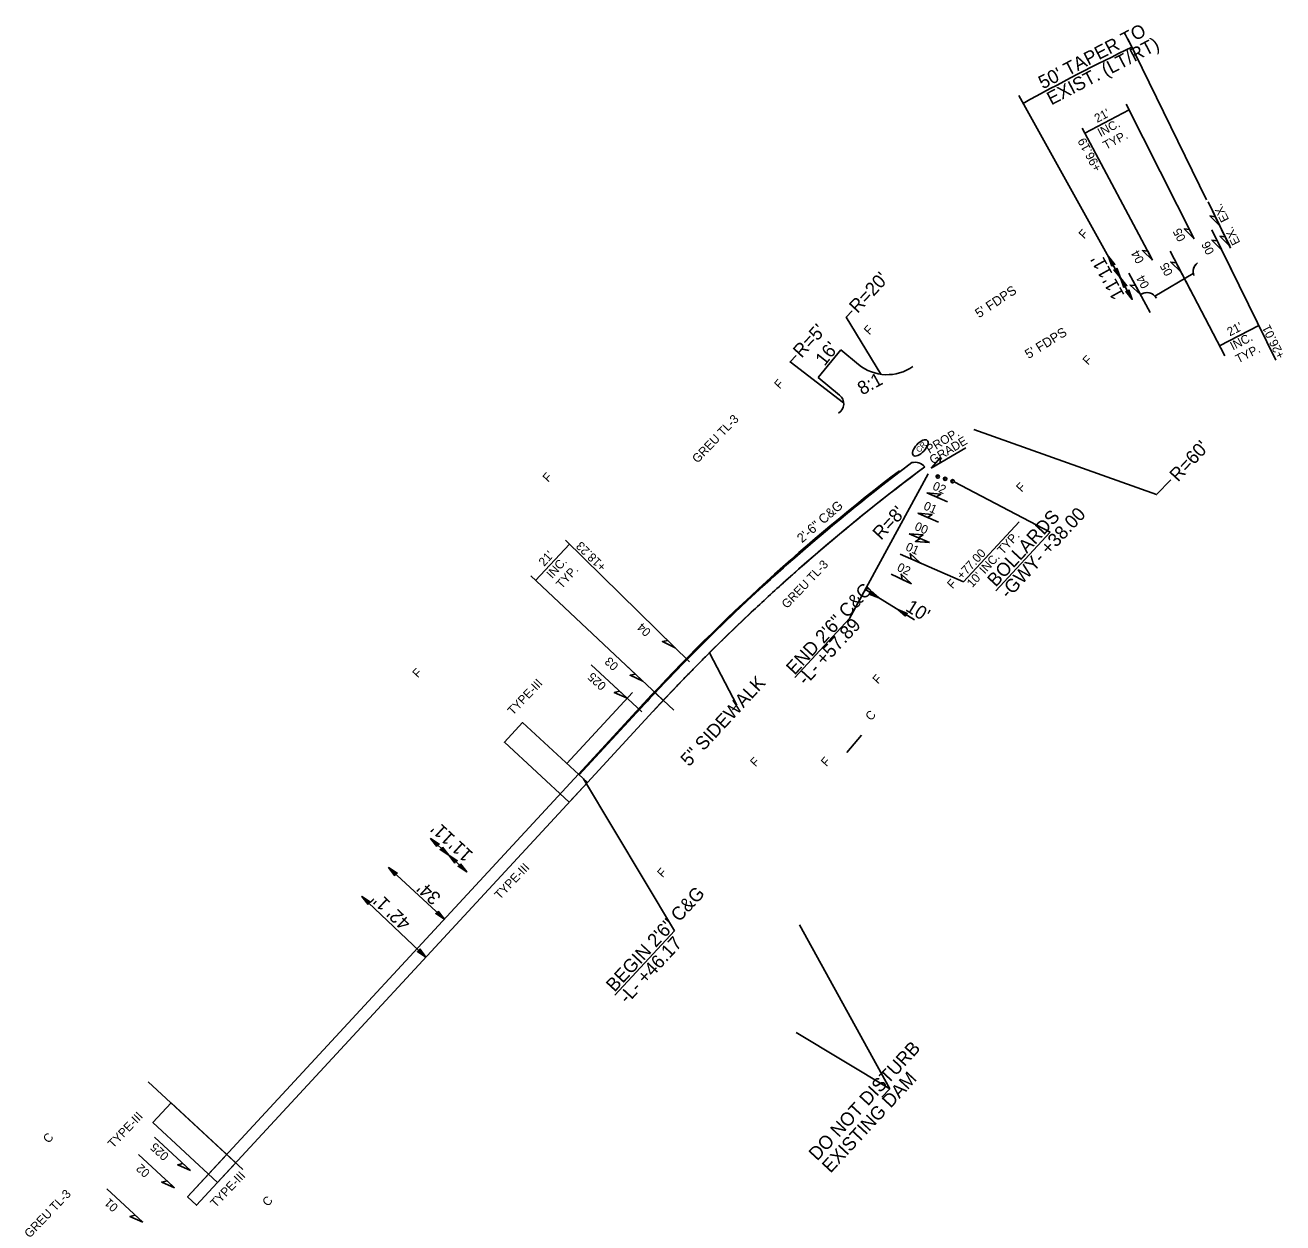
# Model space of a CAD drawing. Extents: x 1768470 to 1769391, y 999727 to 1000666.
# Drawn here: x 1768828 to 1769391, y 1000129 to 1000666 of the extents above; entities that cross this region are included whole.
import ezdxf

# ---------------------------------------------------------------- set-up
doc = ezdxf.new("R2010")
doc.units = 0
for name, color, linetype in [('Cogo Default Point CELL', 7, 'Continuous'), ('COGO Default Point Number', 7, 'Continuous'), ('CTL North Arrow NAD 83 NA 2011 CELL', 7, 'Continuous'), ('CTL North Arrow NAD 83 NSRS CELL', 7, 'Continuous'), ('CTL Sheet Datum Description CELL', 7, 'Continuous'), ('E_ENV_WETLAND_BOUNDARY', 7, 'Continuous'), ('Exist Environmental Wetland Boundary', 7, 'Continuous'), ('Exist Environmental Wetland Boundary Cogo Number', 7, 'Continuous'), ('Exist Hydro Jurisdictional Stream or Body of Water', 7, 'Continuous'), ('Exist Property Line Leader', 7, 'Continuous'), ('P_HYD_TL_Ditch_Lining', 7, 'Continuous'), ('P_HYD_TL_Riprap_Ditch_Bot', 7, 'Continuous'), ('P_NCDOT_Terrain_Contour_Imported', 7, 'Continuous'), ('P_NCDOT_Terrain_Exterior', 7, 'Continuous'), ('Scratch_Level_1', 7, 'Continuous'), ('Scratch_Level_4', 7, 'Continuous'), ('Sheet Symbology CELL', 7, 'Continuous'), ('Sheet Title CELL', 7, 'Continuous')]:
    doc.layers.add(name, color=color, linetype=linetype)

msp = doc.modelspace()

# ---------------------------------------------------------------- linework, layer by layer
at = {"layer": 'Cogo Default Point CELL'}
for p, q in [((1769357.14, 1000587.35), (1769322.01, 1000659.44)), ((1769323.95, 1000542.75), (1769273.09, 1000634.05))]:
    msp.add_line(p, q, dxfattribs=at)
msp.add_arc((1769722.55, 999824.4), 921.98, 115.61226, 119.03268, dxfattribs=at)
at = {"layer": 'CTL North Arrow NAD 83 NA 2011 CELL'}
for points in [[(1769050.9, 1000353.24), (1769079.91, 1000326.43), (1769071.76, 1000317.62), (1769042.76, 1000344.43)], [(1768893.42, 1000182.87), (1768922.43, 1000156.06), (1768914.29, 1000147.25), (1768885.28, 1000174.06)]]:
    msp.add_lwpolyline(points, close=True, dxfattribs=at)
at = {"layer": 'CTL North Arrow NAD 83 NSRS CELL'}
for p, q in [((1769110.26, 1000366.59), (1769113.9, 1000363.16)), ((1769113.9, 1000363.16), (1769110.26, 1000366.59))]:
    msp.add_line(p, q, dxfattribs=at)
msp.add_lwpolyline([(1769109.26, 1000358.18), (1769079.91, 1000326.43), (1769075.87, 1000330.16), (1769076.24, 1000329.82), (1769105.58, 1000361.57)], dxfattribs=at)
msp.add_lwpolyline([(1768900.84, 1000140.8), (1768904.88, 1000137.07), (1769079.91, 1000326.43), (1769075.87, 1000330.16)], close=True, dxfattribs=at)
for centre, radius, start, end in [((1769763.92, 999753.04), 896.5, 126.9363, 136.8132), ((1769226.58, 1000463.78), 6, 41.678, 103.4563), ((1769763.92, 999753.04), 891.5, 126.70564, 130.88594), ((1769763.92, 999753.04), 891.5, 131.89099, 133.23105), ((1769763.92, 999753.04), 891.5, 134.01351, 134.23609), ((1769763.92, 999753.04), 891.5, 134.90564, 134.90612), ((1769763.92, 999753.04), 891.5, 134.57111, 134.57501), ((1769763.92, 999753.04), 891.5, 135.91117, 136.24618), ((1769763.92, 999753.04), 896.5, 136.8132, 137.25123)]:
    msp.add_arc(centre, radius, start, end, dxfattribs=at)
for points, degree in [([(1769180.38, 1000427.03), (1769179.07, 1000425.89), (1769176.45, 1000423.61), (1769172.54, 1000420.16), (1769169.94, 1000417.85), (1769168.65, 1000416.69)], 3), ([(1769153.29, 1000402.58), (1769152.03, 1000401.39), (1769150.76, 1000400.2), (1769149.5, 1000399)], 2), ([(1769145.74, 1000395.4), (1769145.32, 1000394.99), (1769144.9, 1000394.59), (1769144.48, 1000394.18)], 2), ([(1769149.5, 1000399), (1769148.25, 1000397.81), (1769146.99, 1000396.6), (1769145.74, 1000395.4)], 2), ([(1769141.99, 1000391.77), (1769140.75, 1000390.56), (1769139.51, 1000389.35), (1769138.27, 1000388.13)], 2), ([(1769134.57, 1000384.46), (1769133.33, 1000383.23), (1769130.88, 1000380.77), (1769127.22, 1000377.06), (1769124.8, 1000374.57), (1769123.59, 1000373.32)], 3), ([(1769138.22, 1000388.08), (1769137, 1000386.88), (1769135.79, 1000385.67), (1769134.57, 1000384.46)], 2), ([(1769119.97, 1000369.57), (1769118.77, 1000368.31), (1769117.57, 1000367.05), (1769116.38, 1000365.79)], 2), ([(1769112.81, 1000361.99), (1769111.62, 1000360.72), (1769110.44, 1000359.45), (1769109.26, 1000358.18)], 2), ([(1769113.9, 1000363.16), (1769113.54, 1000362.77), (1769113.17, 1000362.38), (1769112.81, 1000361.99)], 2), ([(1769116.38, 1000365.79), (1769115.55, 1000364.92), (1769114.72, 1000364.04), (1769113.9, 1000363.16)], 2)]:
    msp.add_open_spline(points, degree=degree, dxfattribs=at)
at = {"layer": 'CTL Sheet Datum Description CELL'}
for p, q in [((1769197.23, 1000399.86), (1769232.53, 1000464.57)), ((1769244.18, 1000461.02), (1769287.12, 1000438.43)), ((1769262.83, 1000412.15), (1769287.12, 1000438.43)), ((1769226.41, 1000399.2), (1769204.85, 1000412.47)), ((1769172.79, 1000373.42), (1769197.23, 1000399.86)), ((1769134.57, 1000384.46), (1769146.75, 1000360.97)), ((1769144.88, 1000358.94), (1769146.75, 1000360.97)), ((1769118.85, 1000259.99), (1769078.2, 1000328.01)), ((1769009.69, 1000301.29), (1769017.77, 1000293.82)), ((1769017.77, 1000293.82), (1769025.85, 1000286.36)), ((1769015.82, 1000265.2), (1768990.84, 1000288.26)), ((1769007.57, 1000248.17), (1768978.92, 1000275.38)), ((1769092.14, 1000231.1), (1769118.85, 1000259.99)), ((1769215.38, 1000189.23), (1769174.82, 1000262.59)), ((1769215.38, 1000189.23), (1769173.34, 1000214.45)), ((1769215.38, 1000189.23), (1769211.72, 1000185.38))]:
    msp.add_line(p, q, dxfattribs=at)
for points in [[(1769198.55, 1000537.66), (1769195.84, 1000534.73), (1769211.3, 1000509.2)], [(1769173.4, 1000517.67), (1769170.69, 1000514.73), (1769194.67, 1000496.45)], [(1769341.27, 1000461.98), (1769334.81, 1000455.34), (1769253.02, 1000484.49)]]:
    msp.add_lwpolyline(points, dxfattribs=at)
at = {"layer": 'Exist Environmental Wetland Boundary Cogo Number'}
for points in [[(1769314.76, 1000557.66), (1769313.25, 1000561.97), (1769316.15, 1000558.41), (1769315.17, 1000558.52)], [(1769317.09, 1000556.67), (1769318.6, 1000552.36), (1769315.7, 1000555.93), (1769316.68, 1000555.81)], [(1769320.11, 1000548.05), (1769318.6, 1000552.36), (1769321.5, 1000548.8), (1769320.52, 1000548.91)], [(1769322.44, 1000547.06), (1769323.95, 1000542.75), (1769321.05, 1000546.32), (1769322.03, 1000546.2)], [(1769206.95, 1000412.09), (1769210.37, 1000409.07), (1769206.1, 1000410.76), (1769207.01, 1000411.14)], [(1769222.32, 1000400.81), (1769218.89, 1000403.83), (1769223.16, 1000402.13), (1769222.25, 1000401.75)], [(1769012.47, 1000297.66), (1769009.69, 1000301.29), (1769013.56, 1000298.8), (1769012.59, 1000298.61)], [(1769014.99, 1000297.45), (1769017.77, 1000293.82), (1769013.9, 1000296.31), (1769014.87, 1000296.5)], [(1769020.55, 1000290.2), (1769017.77, 1000293.82), (1769021.64, 1000291.34), (1769020.67, 1000291.14)], [(1768993.62, 1000284.64), (1768990.84, 1000288.27), (1768994.71, 1000285.78), (1768993.75, 1000285.59)], [(1769023.07, 1000289.98), (1769025.85, 1000286.36), (1769021.98, 1000288.84), (1769022.95, 1000289.04)], [(1768981.66, 1000271.71), (1768978.93, 1000275.37), (1768982.76, 1000272.84), (1768981.79, 1000272.65)], [(1769013.04, 1000268.82), (1769015.82, 1000265.2), (1769011.96, 1000267.68), (1769012.92, 1000267.88)], [(1769004.84, 1000251.83), (1769007.57, 1000248.17), (1769003.74, 1000250.71), (1769004.71, 1000250.89)]]:
    msp.add_lwpolyline(points, close=True, dxfattribs=at)
at = {"layer": 'Exist Hydro Jurisdictional Stream or Body of Water'}
for p, q in [((1769357.91, 1000586.38), (1769367.97, 1000565.72)), ((1769334.04, 1000544.22), (1769351.27, 1000554.37)), ((1769070.73, 1000334.91), (1769100.08, 1000366.66)), ((1769196.14, 1000339.87), (1769202.59, 1000347.52)), ((1768900.84, 1000140.8), (1768904.88, 1000137.07))]:
    msp.add_line(p, q, dxfattribs=at)
msp.add_lwpolyline([(1768900.84, 1000140.8), (1768900.84, 1000140.8), (1768918.39, 1000159.79)], dxfattribs=at)
for centre, start, end in [((1769356.21, 1000555.12), 127.0126, 199.6474), ((1769356.21, 1000555.12), 127.0126, 188.6168), ((1769330.44, 1000540.75), 30.0937, 124.524), ((1769330.44, 1000540.75), 43.9672, 115.437)]:
    msp.add_arc(centre, 5, start, end, dxfattribs=at)
at = {"layer": 'P_HYD_TL_Ditch_Lining'}
for centre, radius in [((1769236.79, 1000463.34), 0.75), ((1769236.79, 1000463.34), 0.05), ((1769240.13, 1000462.32), 0.75), ((1769240.13, 1000462.32), 0.05), ((1769243.48, 1000461.3), 0.75), ((1769243.48, 1000461.3), 0.05)]:
    msp.add_circle(centre, radius, dxfattribs=at)
at = {"layer": 'P_HYD_TL_Riprap_Ditch_Bot'}
msp.add_ellipse((1769229, 1000476.21), major_axis=(3.11, 3.37), ratio=0.462467, dxfattribs=at)
at = {"layer": 'P_NCDOT_Terrain_Contour_Imported'}
for p, q in [((1769368.41, 1000555.91), (1769359.57, 1000573.85)), ((1769340.84, 1000564.36), (1769350.09, 1000546.62)), ((1769322.34, 1000554.43), (1769331.99, 1000536.92)), ((1769125.58, 1000380.37), (1769111.31, 1000394.39)), ((1769118.64, 1000358.71), (1769096.77, 1000379.25)), ((1769089.61, 1000371.55), (1769104.3, 1000357.97))]:
    msp.add_line(p, q, dxfattribs=at)
at = {"layer": 'P_NCDOT_Terrain_Exterior'}
for p, q in [((1769302.68, 1000617.13), (1769322.54, 1000627.67)), ((1769321.26, 1000630.19), (1769351.68, 1000569.91)), ((1769301.43, 1000619.46), (1769333.04, 1000560.24)), ((1769358.34, 1000585.5), (1769363.16, 1000575.61)), ((1769363.16, 1000575.61), (1769367.59, 1000566.51)), ((1769359.57, 1000573.85), (1769388.29, 1000515.55)), ((1769340.84, 1000564.36), (1769365.33, 1000517.4)), ((1769322.34, 1000554.43), (1769327.6, 1000544.87)), ((1769362.94, 1000521.99), (1769380.64, 1000531.08)), ((1769233.86, 1000467.11), (1769249.39, 1000476.31)), ((1769241.13, 1000452.11), (1769231.96, 1000456.12)), ((1769227.96, 1000446.96), (1769237.12, 1000442.95)), ((1769248.4, 1000416.2), (1769273.33, 1000443.17)), ((1769070.15, 1000434.84), (1769119.16, 1000386.68)), ((1769223.95, 1000437.8), (1769233.11, 1000433.79)), ((1769056.72, 1000416.86), (1769071.9, 1000433.12)), ((1769219.94, 1000428.64), (1769248.4, 1000416.2)), ((1769054.56, 1000418.86), (1769104.79, 1000371.72)), ((1769216, 1000419.65), (1769225.01, 1000415.3)), ((1769081.54, 1000379.01), (1769097.69, 1000364.08)), ((1768886, 1000167.47), (1768902.15, 1000152.54)), ((1768878.87, 1000159.76), (1768895.03, 1000144.83)), ((1768864.62, 1000144.34), (1768880.77, 1000129.41))]:
    msp.add_line(p, q, dxfattribs=at)
for points in [[(1769363.16, 1000575.61), (1769358.73, 1000580.13), (1769361.13, 1000579.76)], [(1769351.68, 1000569.91), (1769347.19, 1000574.37), (1769349.6, 1000574.04)], [(1769367.58, 1000566.51), (1769363.16, 1000571.03), (1769365.56, 1000570.67)], [(1769333.04, 1000560.24), (1769328.45, 1000564.59), (1769330.86, 1000564.32)], [(1769364.03, 1000564.81), (1769359.58, 1000569.31), (1769361.98, 1000568.96)], [(1769345.7, 1000555.05), (1769341.15, 1000559.45), (1769343.56, 1000559.15)], [(1769327.6, 1000544.87), (1769322.96, 1000549.16), (1769325.37, 1000548.92)], [(1769233.86, 1000467.11), (1769238, 1000471.89), (1769237.84, 1000469.47)], [(1769231.96, 1000456.12), (1769238.26, 1000455.55), (1769236.2, 1000454.27)], [(1769227.96, 1000446.96), (1769234.26, 1000446.39), (1769232.19, 1000445.11)], [(1769223.95, 1000437.8), (1769230.25, 1000437.23), (1769228.19, 1000435.95)], [(1769233.11, 1000433.79), (1769226.81, 1000434.36), (1769228.87, 1000435.64)], [(1769229.1, 1000424.63), (1769224.41, 1000428.87), (1769224.87, 1000426.48)], [(1769225.01, 1000415.3), (1769220.47, 1000419.71), (1769220.84, 1000417.31)], [(1769119.16, 1000386.68), (1769113.48, 1000389.46), (1769115.86, 1000389.92)], [(1769104.79, 1000371.72), (1769099.04, 1000374.37), (1769101.42, 1000374.88)], [(1769097.69, 1000364.08), (1769091.93, 1000366.68), (1769094.29, 1000367.22)], [(1768902.15, 1000152.54), (1768896.39, 1000155.14), (1768898.76, 1000155.68)], [(1768895.03, 1000144.83), (1768889.26, 1000147.43), (1768891.63, 1000147.97)], [(1768880.77, 1000129.41), (1768875.01, 1000132.01), (1768877.38, 1000132.55)]]:
    msp.add_lwpolyline(points, close=True, dxfattribs=at)
at = {"layer": 'Scratch_Level_1'}
for p, q in [((1769239.88, 1000461.75), (1769240.15, 1000462.36)), ((1769075.87, 1000330.16), (1769105.22, 1000361.91)), ((1769075.87, 1000330.16), (1769105.22, 1000361.91)), ((1769075.87, 1000330.16), (1769105.22, 1000361.91)), ((1769076.24, 1000329.82), (1769105.58, 1000361.57)), ((1769076.24, 1000329.82), (1769105.58, 1000361.57)), ((1769079.91, 1000326.43), (1769109.26, 1000358.18)), ((1769079.91, 1000326.43), (1769109.26, 1000358.18))]:
    msp.add_line(p, q, dxfattribs=at)
for radius, start in [(896.5, 126.9363), (897, 127.35967), (897, 127.35967), (897, 127.35967), (896.5, 127.35967), (891.5, 126.70564), (891.5, 127.35967)]:
    msp.add_arc((1769763.92, 999753.04), radius, start, 137.25123, dxfattribs=at)
at = {"layer": 'Scratch_Level_4'}
msp.add_line((1768925.61, 1000153.12), (1768883.14, 1000192.38), dxfattribs=at)
at = {"layer": 'Sheet Symbology CELL'}
for p, q in [((1769183.27, 1000507.78), (1769193.46, 1000520.11)), ((1769193.46, 1000520.11), (1769201.37, 1000513.58)), ((1769183.27, 1000507.78), (1769192.87, 1000499.85))]:
    msp.add_line(p, q, dxfattribs=at)
for centre, radius, start, end in [((1769214.11, 1000529), 20, 230.4423, 305.3195), ((1769189.69, 1000495.99), 5, 302.0792, 50.4423)]:
    msp.add_arc(centre, radius, start, end, dxfattribs=at)
at = {"layer": 'Sheet Title CELL'}
for points in [[(1769042.76, 1000344.43), (1769071.76, 1000317.62), (1769079.91, 1000326.43), (1769050.9, 1000353.24)], [(1768885.28, 1000174.06), (1768914.29, 1000147.25), (1768922.43, 1000156.06), (1768893.42, 1000182.87)]]:
    msp.add_lwpolyline(points, close=True, dxfattribs=at)

# ---------------------------------------------------------------- texts
at = {"layer": 'Cogo Default Point CELL'}
for s, height, rotation, p in [("50' TAPER TO", 6, 27.6042, (1769283.89, 1000636.73)), ('EXIST. (LT/RT)', 6, 27.6042, (1769287.65, 1000629.55)), ("11'", 6, 119.1231, (1769315.3, 1000554.28)), ("R=20'", 6, 47.2512, (1769200.93, 1000536.15)), ("5' FDPS", 4.2, 33.7903, (1769255.3, 1000534.22)), ("11'", 6, 119.1231, (1769320.65, 1000544.67)), ("R=5'", 6, 47.2512, (1769175.77, 1000516.15)), ("5' FDPS", 4.2, 31.9258, (1769277.48, 1000515.96)), ("16'", 6, 51.5185, (1769186.13, 1000512.57)), ('8:1', 6, 28.8107, (1769202.96, 1000499.67)), ("R=60'", 6, 47.2512, (1769344.44, 1000460.67)), ('2\'-6" C&G', 4.2, 41.1838, (1769176.01, 1000433.43)), ("R=8'", 6, 47.2512, (1769211.41, 1000434.62)), ('BOLLARDS', 6, 47.2512, (1769262.78, 1000413.61)), ('-GWY- +38.00', 6, 47.2512, (1769268.51, 1000408.32)), ('END 2\'6" C&G', 6, 47.2512, (1769172.71, 1000374.19)), ("10'", 6, 328.3797, (1769221.99, 1000403.55)), ('-L- +57.89', 6, 47.2512, (1769177.77, 1000369.51)), ('5" SIDEWALK', 6, 47.2512, (1769125.42, 1000333.2)), ("11'", 6, 137.282, (1769020.99, 1000302.08)), ("11'", 6, 137.282, (1769029.07, 1000294.62)), ("34'", 6, 137.282, (1769014.72, 1000275.37)), ('BEGIN 2\'6" C&G', 6, 47.2512, (1769092.05, 1000232.22)), ("42' 1''", 6, 136.4805, (1769001.23, 1000263.9)), ('-L- +46.17', 6, 47.2512, (1769097.78, 1000226.92)), ('DO NOT DISTURB', 6, 47.2512, (1769182.82, 1000156.64)), ('EXISTING DAM', 6, 47.2512, (1769188.77, 1000151.14))]:
    msp.add_text(s, height=height, rotation=rotation, dxfattribs=at).set_placement(p)
at = {"layer": 'COGO Default Point Number'}
for p in [(1769206.85, 1000353.73), (1768838.52, 1000164.53), (1768936.73, 1000136.21)]:
    msp.add_text('C', height=3.9, rotation=47.2512, dxfattribs=at).set_placement(p)
at = {"layer": 'E_ENV_WETLAND_BOUNDARY'}
for s, p in [('GREU TL-3', (1769129.22, 1000469.14)), ('GREU TL-3', (1769169.28, 1000404)), ('TYPE-III', (1769046.52, 1000356.23)), ('TYPE-III', (1769040.67, 1000273.74)), ('TYPE-III', (1768867.52, 1000162.33)), ('TYPE-III', (1768913.4, 1000135.73)), ('GREU TL-3', (1768830.12, 1000122.11))]:
    msp.add_text(s, height=3.9, rotation=46.4043, dxfattribs=at).set_placement(p)
at = {"layer": 'Exist Environmental Wetland Boundary'}
for s, rotation, p in [("21'", 27.9437, (1769308.22, 1000621.72)), ('INC.', 27.9437, (1769309.69, 1000615.41)), ('+96.19', 118.0928, (1769310.29, 1000601.32)), ('TYP.', 27.9437, (1769312.16, 1000609.64)), ('EX.', 116.7128, (1769367.38, 1000578.5)), ('EX.', 116.7128, (1769372.39, 1000568.2)), ('05', 117.2396, (1769348.04, 1000569.91)), ('04', 118.5546, (1769329.4, 1000560.15)), ('06', 116.6873, (1769360.79, 1000564.01)), ('05', 118.0023, (1769342.29, 1000554.55)), ('04', 119.3173, (1769331.77, 1000549)), ("21'", 27.1652, (1769367.62, 1000526.12)), ('+26.01', 115.9451, (1769392.4, 1000517.31)), ('INC.', 27.1652, (1769369.01, 1000519.8)), ('TYP.', 27.1652, (1769371.4, 1000513.99)), ('PROP.', 31.0677, (1769233.06, 1000473.53)), ('GRADE', 31.0677, (1769234.57, 1000468.74)), ('02', 336.8345, (1769234.16, 1000457.74)), ('01', 336.8345, (1769230.11, 1000448.83)), ('00', 336.8345, (1769226.11, 1000439.67)), ("10' INC. TYP.", 47.2512, (1769252.28, 1000413.41)), ("21'", 47.8073, (1769060.54, 1000422.9)), ('+18.23', 135.4982, (1769088.62, 1000423.33)), ('01', 336.8345, (1769222.1, 1000430.5)), ('+77.00', 47.2512, (1769247.72, 1000416.98)), ('INC.', 47.8073, (1769064.07, 1000417.47)), ('02', 334.6798, (1769218.23, 1000421.44)), ('TYP.', 47.8073, (1769068.35, 1000412.88)), ('04', 135.96, (1769108.67, 1000394.16)), ('03', 137.275, (1769094.13, 1000378.95)), ('025', 137.7129, (1769088.67, 1000370.13)), ('025', 137.7129, (1768892.76, 1000159.52)), ('02', 137.7129, (1768884.31, 1000151.98)), ('01', 137.7129, (1768870.06, 1000136.56))]:
    msp.add_text(s, height=3.9, rotation=rotation, dxfattribs=at).set_placement(p)
at = {"layer": 'Exist Property Line Leader'}
for p in [(1769302.36, 1000569.56), (1769206.17, 1000526.57), (1769304.14, 1000513.05), (1769166.01, 1000502.36), (1769062.29, 1000460.61), (1769274.37, 1000456.15), (1769243.43, 1000412.86), (1769003.98, 1000372.95), (1769210.03, 1000370.22), (1769155.23, 1000333.11), (1769186.92, 1000333.24), (1769113.6, 1000283.5)]:
    msp.add_text('F', height=3.9, rotation=47.2512, dxfattribs=at).set_placement(p)
at = {"layer": 'P_HYD_TL_Riprap_Ditch_Bot'}
msp.add_text('CR', height=2.452, rotation=47.2512, dxfattribs=at).set_placement((1769228.58, 1000473.97))

doc.saveas('drawing.dxf')
